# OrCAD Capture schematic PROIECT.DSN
size A
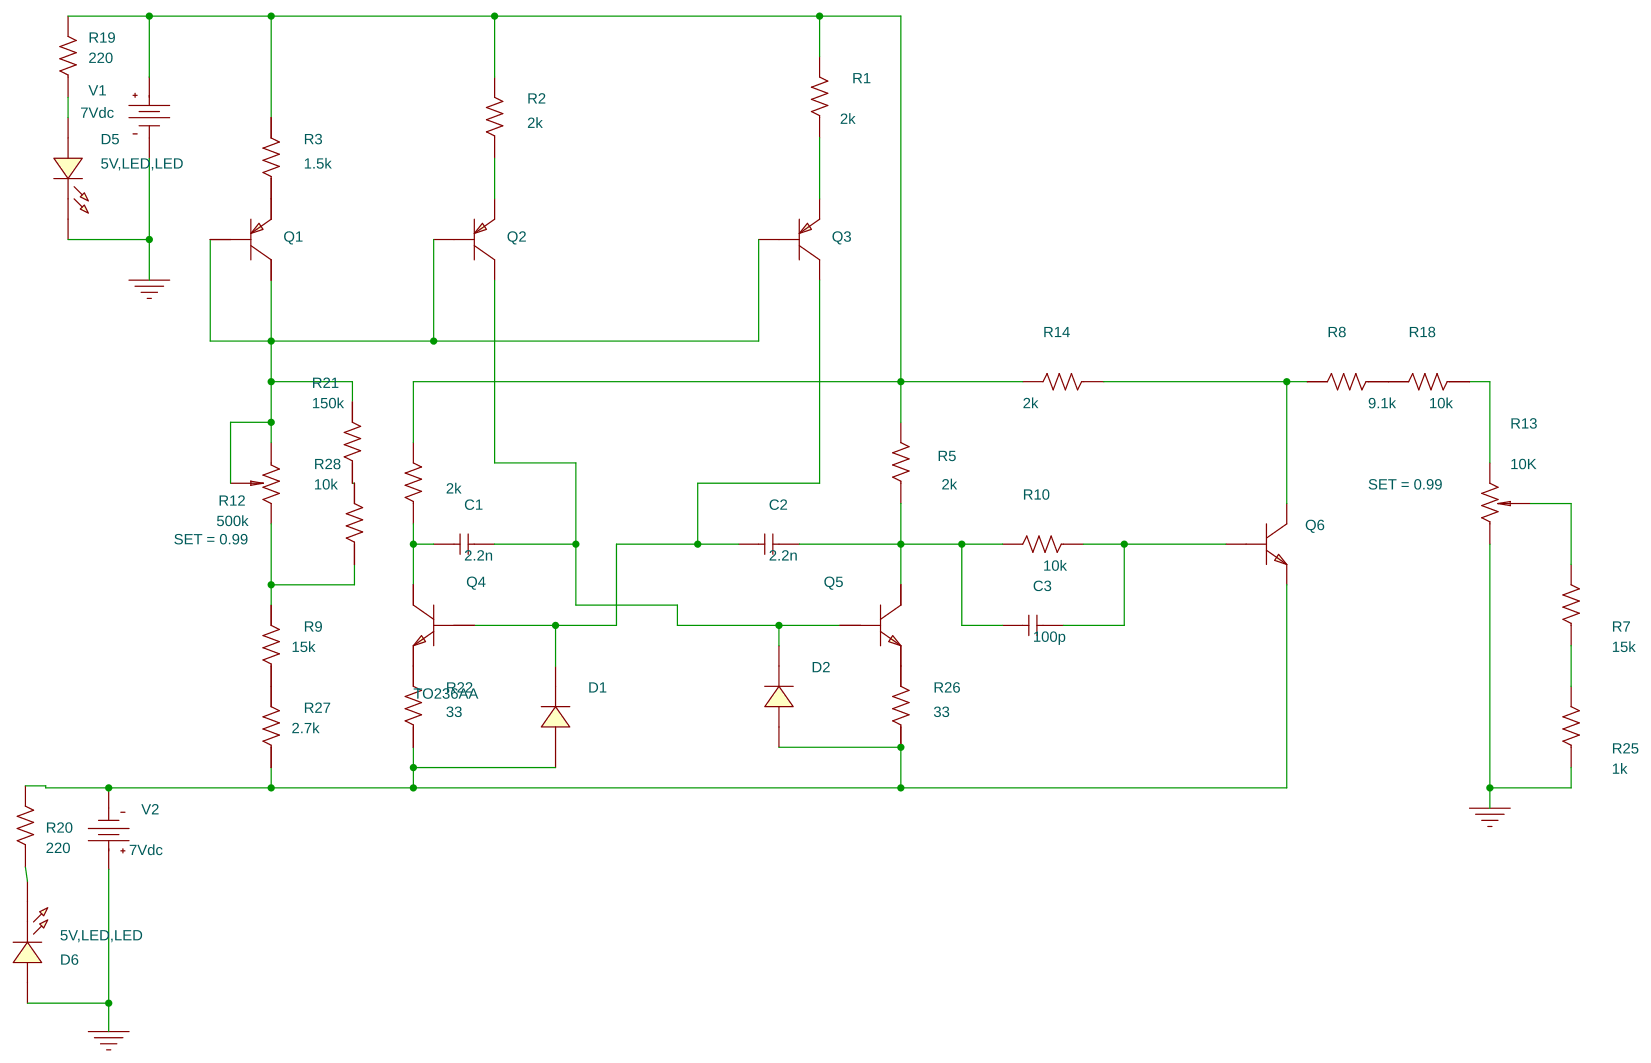
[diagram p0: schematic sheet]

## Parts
C1  2.2n  [CAPC2008X126N_0805]
C2  2.2n  [CAPC2008X126N_0805]
C3  100p  [CAPC2008X126N_0805]
D1  BZX84-C5V6  [TO236AA]
D2  BZX84-C5V6  [TO236AA]
D5  5V,LED,LED  [DIOM2012X160M
0805]
D6  5V,LED,LED  [DIOM2012X160M]
Q1  QBC856B  [TO236AA]
Q2  QBC856B  [TO236AA]
Q3  QBC856B  [TO236AA]
Q4  QBC846B  [TO236AA]
Q5  QBC846B  [TO236AA]
Q6  QBC846B  [TO236AA]
R1  2k  [RES2012X50N_0805]
R2  2k  [RES2012X50N_0805]
R3  1.5k  [RES2012X50N_0805]
R4  2k  [RES2012X50N_0805]
R5  2k  [RES2012X50N_0805]
R7  15k  [RES2012X50N_0805]
R8  9.1k  [RES2012X50N_0805]
R9  15k  [RES2012X50N_0805]
R10  10k  [RES2012X50N_0805]
R12  500k  [TS53YL]
R13  10K  [TS53YL]
R14  2k  [RES2012X50N_0805]
R18  10k  [RES2012X50N_0805]
R19  220  [RES2012X50N_0805]
R20  220  [RES2012X50N_0805]
R21  150k  [RES2012X50N_0805]
R22  33  [RES2012X50N_0805]
R25  1k  [RES2012X50N_0805]
R26  33  [RES2012X50N_0805]
R27  2.7k  [RES2012X50N_0805]
R28  10k  [RES2012X50N_0805]
V1  VDC
V2  VDC

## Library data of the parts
C1-C3 = C
D1 D2 = BZX84-C5V6
D5 D6 = LED: AppProp: mN=LED,fV=3,fC=30E-3; BV: 5; IBV: 10e-6; IF: 160E-3; IS: 2.6404e-027; PDM: 114E-3; RS: 2; VR: 5
Q1-Q3 = QBC856B
Q4-Q6 = QBC846B
R1-R5 R7-R10 R14 R18-R22 R25-R28 = R
R12 R13 = POT: SET: 0.99
V1 V2 = VDC: DC: 7Vdc

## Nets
0: D5.2 D6.1 R13.1 R25.1 V1.1(-) V2.0(+)
N00365: R1.2 R2.2 R3.2 R4.2 R5.2 R14.2 R19.2 V1.0(+)
N00611: Q1.2(B) Q1.3(C) Q2.2(B) Q3.2(B) R12.1 R12.2(t) R21.2
N00680: Q2.1(E) R2.1
N00723: Q3.1(E) R1.1
N00817: C2.2 C3.1 Q5.3(C) R5.1 R10.2
N00853: C2.1 D1.1(C) Q3.3(C) Q4.2(B)
N00865: C1.2 D2.1(C) Q2.3(C) Q5.2(B)
N01850: D1.2(A) D2.2(A) Q6.1(E) R20.2 R22.1 R26.1 R27.1 V2.1(-)
N17376: R9.2 R12.3(2) R28.1
N50446: C1.1 Q4.3(C) R4.1
N64104: Q6.3(C) R8.2 R14.1
N64114: R13.3(2) R18.1
N64220: C3.2 Q6.2(B) R10.1
N66860: R7.1 R25.2
N67873: R7.2 R13.2(t)
N73561: D5.1 R19.1
N74199: D6.2 R20.1
N85526: R21.1 R28.2
N91177: Q1.1(E) R3.1
N91322: R9.1 R27.2
N91438: Q4.1(E) R22.2
N91571: Q5.1(E) R26.2
N91642: R8.1 R18.2
